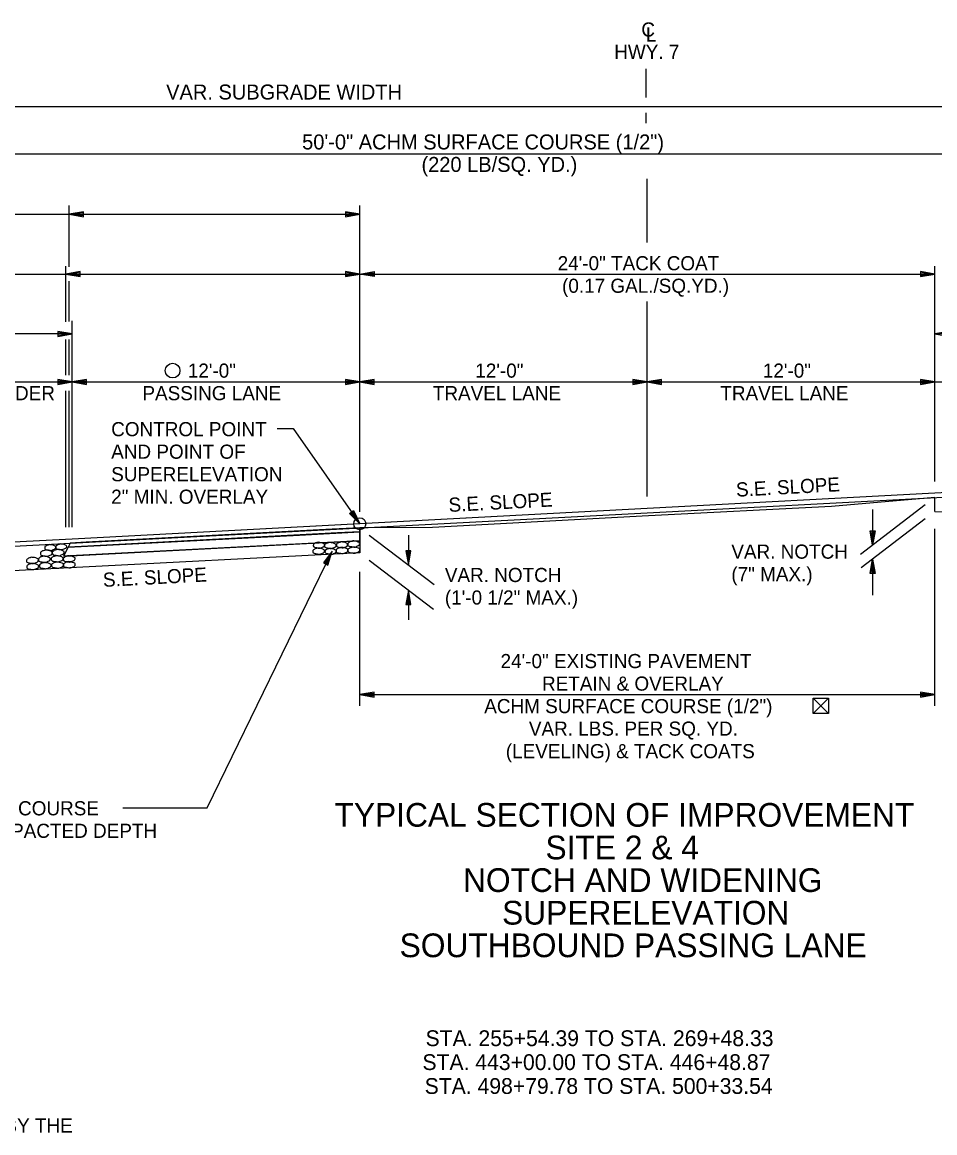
# Model space of a CAD drawing. Extents: x 1398183 to 1398373, y 1967240 to 1968889.
# Drawn here: x 1398222.36 to 1398260.45, y 1968068.4 to 1968114.76 of the extents above; entities that cross this region are included whole.
import ezdxf

# ---------------------------------------------------------------- set-up
doc = ezdxf.new("R2010")
doc.units = 0
for name, color, linetype in [('1', 7, 'Continuous'), ('10', 7, 'Continuous'), ('19', 7, 'Continuous'), ('42', 7, 'Continuous'), ('7', 7, 'Continuous'), ('Level 1', 7, 'Continuous'), ('Level 9', 7, 'Continuous')]:
    doc.layers.add(name, color=color, linetype=linetype)

# ---------------------------------------------------------------- blocks, each defined once
blk = doc.blocks.new('ROCKS')
at = {"layer": '1'}
blk.add_spline([(0.013, 0.06), (0.053, 0.053), (0.107, 0.033), (0.133, 0.013), (0.133, -0.007), (0.12, -0.033), (0.107, -0.04), (0.073, -0.053), (0.033, -0.067), (0.013, -0.067), (-0.02, -0.06), (-0.06, -0.053), (-0.087, -0.047), (-0.113, -0.02), (-0.113, -0.007), (-0.107, 0.02), (-0.087, 0.033), (-0.067, 0.047), (-0.033, 0.053), (-0.02, 0.06), (0.013, 0.06)], degree=3, dxfattribs=at)

msp = doc.modelspace()

# ---------------------------------------------------------------- linework, layer by layer
at = {"layer": '10'}
for p, q in [((1398256.012, 1968086.545), (1398255.37, 1968085.904)), ((1398255.37, 1968086.545), (1398256.012, 1968085.904)), ((1398255.63, 1968085.904), (1398255.619, 1968085.904))]:
    msp.add_line(p, q, dxfattribs=at)
msp.add_lwpolyline([(1398255.619, 1968085.904), (1398255.37, 1968085.904), (1398255.37, 1968086.545), (1398256.012, 1968086.545), (1398256.012, 1968085.904), (1398255.63, 1968085.904)], dxfattribs=at)
msp.add_circle((1398228.634, 1968100.217), 0.306, dxfattribs=at)
at = {"layer": '19'}
for p, q in [((1398212.441, 1968111.247), (1398274.281, 1968111.247)), ((1398268.448, 1968109.247), (1398218.448, 1968109.247)), ((1398224.318, 1968104.556), (1398224.318, 1968107.106)), ((1398236.446, 1968094.324), (1398236.446, 1968107.106)), ((1398206.204, 1968106.747), (1398236.446, 1968106.747)), ((1398224.918, 1968106.852), (1398224.318, 1968106.747)), ((1398224.318, 1968106.747), (1398224.918, 1968106.642)), ((1398224.918, 1968106.797), (1398224.478, 1968106.762)), ((1398224.478, 1968106.732), (1398224.918, 1968106.692)), ((1398224.918, 1968106.642), (1398224.918, 1968106.852)), ((1398235.846, 1968106.852), (1398235.846, 1968106.642)), ((1398236.446, 1968106.747), (1398235.846, 1968106.852)), ((1398236.286, 1968106.762), (1398235.846, 1968106.797)), ((1398235.846, 1968106.642), (1398236.446, 1968106.747)), ((1398235.846, 1968106.692), (1398236.286, 1968106.732)), ((1398207.393, 1968104.247), (1398260.446, 1968104.247)), ((1398224.179, 1968102.248), (1398224.18, 1968104.572)), ((1398224.78, 1968104.352), (1398224.18, 1968104.247)), ((1398224.18, 1968104.247), (1398224.78, 1968104.142)), ((1398224.78, 1968104.297), (1398224.34, 1968104.262)), ((1398224.34, 1968104.232), (1398224.78, 1968104.192)), ((1398224.78, 1968104.142), (1398224.78, 1968104.352)), ((1398235.846, 1968104.352), (1398235.846, 1968104.142)), ((1398236.446, 1968104.247), (1398235.846, 1968104.352)), ((1398236.286, 1968104.262), (1398235.846, 1968104.297)), ((1398235.846, 1968104.142), (1398236.446, 1968104.247)), ((1398235.846, 1968104.192), (1398236.286, 1968104.232)), ((1398236.446, 1968104.247), (1398237.046, 1968104.352)), ((1398237.046, 1968104.142), (1398236.446, 1968104.247)), ((1398236.606, 1968104.262), (1398237.046, 1968104.297)), ((1398237.046, 1968104.192), (1398236.606, 1968104.232)), ((1398237.046, 1968104.352), (1398237.046, 1968104.142)), ((1398259.846, 1968104.352), (1398259.846, 1968104.142)), ((1398260.446, 1968104.247), (1398259.846, 1968104.352)), ((1398260.286, 1968104.262), (1398259.846, 1968104.297)), ((1398259.846, 1968104.142), (1398260.446, 1968104.247)), ((1398259.846, 1968104.192), (1398260.286, 1968104.232)), ((1398260.446, 1968095.596), (1398260.446, 1968104.572)), ((1398224.318, 1968102.266), (1398224.318, 1968103.949)), ((1398224.446, 1968093.688), (1398224.446, 1968102.294)), ((1398224.446, 1968101.747), (1398206.446, 1968101.747)), ((1398223.846, 1968101.852), (1398223.846, 1968101.642)), ((1398224.446, 1968101.747), (1398223.846, 1968101.852)), ((1398224.286, 1968101.762), (1398223.846, 1968101.797)), ((1398223.846, 1968101.642), (1398224.446, 1968101.747)), ((1398223.846, 1968101.692), (1398224.286, 1968101.732)), ((1398224.181, 1968100.029), (1398224.181, 1968101.517)), ((1398224.318, 1968100.032), (1398224.318, 1968101.52)), ((1398261.046, 1968101.852), (1398260.446, 1968101.747)), ((1398284.446, 1968101.747), (1398260.446, 1968101.747)), ((1398260.446, 1968101.747), (1398261.046, 1968101.642)), ((1398218.445, 1968099.747), (1398224.445, 1968099.747)), ((1398223.846, 1968099.852), (1398223.846, 1968099.642)), ((1398224.446, 1968099.747), (1398223.846, 1968099.852)), ((1398224.286, 1968099.762), (1398223.846, 1968099.797)), ((1398223.846, 1968099.642), (1398224.446, 1968099.747)), ((1398223.846, 1968099.692), (1398224.286, 1968099.732)), ((1398225.046, 1968099.852), (1398224.446, 1968099.747)), ((1398224.446, 1968099.747), (1398225.046, 1968099.642)), ((1398224.446, 1968099.747), (1398236.446, 1968099.747)), ((1398225.046, 1968099.797), (1398224.606, 1968099.762)), ((1398224.606, 1968099.732), (1398225.046, 1968099.692)), ((1398225.046, 1968099.642), (1398225.046, 1968099.852)), ((1398235.846, 1968099.852), (1398235.846, 1968099.642)), ((1398236.446, 1968099.747), (1398235.846, 1968099.852)), ((1398236.286, 1968099.762), (1398235.846, 1968099.797)), ((1398235.846, 1968099.642), (1398236.446, 1968099.747)), ((1398235.846, 1968099.692), (1398236.286, 1968099.732)), ((1398237.046, 1968099.852), (1398236.446, 1968099.747)), ((1398236.446, 1968099.747), (1398237.046, 1968099.642)), ((1398236.446, 1968099.747), (1398248.446, 1968099.747)), ((1398237.046, 1968099.797), (1398236.606, 1968099.762)), ((1398236.606, 1968099.732), (1398237.046, 1968099.692)), ((1398237.046, 1968099.642), (1398237.046, 1968099.852)), ((1398247.846, 1968099.852), (1398247.846, 1968099.642)), ((1398248.446, 1968099.747), (1398247.846, 1968099.852)), ((1398248.286, 1968099.762), (1398247.846, 1968099.797)), ((1398247.846, 1968099.642), (1398248.446, 1968099.747)), ((1398247.846, 1968099.692), (1398248.286, 1968099.732)), ((1398249.046, 1968099.852), (1398248.446, 1968099.747)), ((1398248.446, 1968099.747), (1398249.046, 1968099.642)), ((1398248.446, 1968099.747), (1398260.446, 1968099.747)), ((1398249.046, 1968099.797), (1398248.606, 1968099.762)), ((1398248.606, 1968099.732), (1398249.046, 1968099.692)), ((1398249.046, 1968099.642), (1398249.046, 1968099.852)), ((1398259.846, 1968099.852), (1398259.846, 1968099.642)), ((1398260.446, 1968099.747), (1398259.846, 1968099.852)), ((1398260.286, 1968099.762), (1398259.846, 1968099.797)), ((1398259.846, 1968099.642), (1398260.446, 1968099.747)), ((1398259.846, 1968099.692), (1398260.286, 1968099.732)), ((1398260.446, 1968099.747), (1398268.446, 1968099.747)), ((1398224.181, 1968093.688), (1398224.181, 1968099.376)), ((1398224.318, 1968093.688), (1398224.318, 1968099.373)), ((1398260.049, 1968094.611), (1398257.346, 1968092.542)), ((1398260.446, 1968094.338), (1398260.446, 1968094.921)), ((1398236.016, 1968094.255), (1398236.187, 1968094.374)), ((1398236.446, 1968093.824), (1398236.016, 1968094.255)), ((1398236.346, 1968093.948), (1398236.063, 1968094.282)), ((1398236.152, 1968094.345), (1398236.366, 1968093.964)), ((1398236.187, 1968094.374), (1398236.446, 1968093.824)), ((1398260.049, 1968094.034), (1398257.367, 1968091.981)), ((1398257.848, 1968094.426), (1398257.848, 1968092.926)), ((1398260.446, 1968094.338), (1398274.28, 1968094.061)), ((1398236.446, 1968093.655), (1398236.446, 1968093.488)), ((1398260.446, 1968086.222), (1398260.446, 1968093.612)), ((1398236.446, 1968093.113), (1398224.086, 1968092.469)), ((1398224.276, 1968092.848), (1398236.446, 1968093.488)), ((1398235.522, 1968093.441), (1398224.833, 1968092.878)), ((1398236.446, 1968093.488), (1398235.522, 1968093.441)), ((1398235.542, 1968093.066), (1398236.446, 1968093.113)), ((1398236.446, 1968093.488), (1398236.446, 1968093.113)), ((1398236.446, 1968093.113), (1398236.446, 1968093.488)), ((1398236.446, 1968093.113), (1398236.446, 1968092.613)), ((1398236.843, 1968093.351), (1398239.545, 1968091.283)), ((1398238.474, 1968093.352), (1398238.474, 1968092.102)), ((1398257.743, 1968093.526), (1398257.953, 1968093.526)), ((1398257.848, 1968092.926), (1398257.743, 1968093.526)), ((1398257.833, 1968093.086), (1398257.793, 1968093.526)), ((1398257.953, 1968093.526), (1398257.848, 1968092.926)), ((1398257.898, 1968093.526), (1398257.863, 1968093.086)), ((1398224.276, 1968092.848), (1398224.086, 1968092.469)), ((1398224.361, 1968093.018), (1398224.276, 1968092.848)), ((1398230.081, 1968081.974), (1398235.293, 1968092.681)), ((1398235.293, 1968092.681), (1398234.929, 1968092.192)), ((1398235.116, 1968092.1), (1398235.293, 1968092.681)), ((1398238.579, 1968092.702), (1398238.369, 1968092.702)), ((1398238.369, 1968092.702), (1398238.474, 1968092.102)), ((1398238.424, 1968092.702), (1398238.459, 1968092.262)), ((1398238.474, 1968092.102), (1398238.579, 1968092.702)), ((1398238.489, 1968092.262), (1398238.529, 1968092.702)), ((1398234.929, 1968092.192), (1398235.116, 1968092.1)), ((1398235.21, 1968092.545), (1398234.978, 1968092.171)), ((1398235.072, 1968092.123), (1398235.235, 1968092.532)), ((1398236.843, 1968092.309), (1398239.524, 1968090.257)), ((1398257.743, 1968091.749), (1398257.848, 1968092.349)), ((1398257.793, 1968091.749), (1398257.833, 1968092.189)), ((1398257.848, 1968092.349), (1398257.953, 1968091.749)), ((1398257.848, 1968092.349), (1398257.848, 1968090.849)), ((1398257.863, 1968092.189), (1398257.898, 1968091.749)), ((1398236.446, 1968086.222), (1398236.446, 1968091.822)), ((1398257.953, 1968091.749), (1398257.743, 1968091.749)), ((1398238.474, 1968091.06), (1398238.369, 1968090.46)), ((1398238.459, 1968090.9), (1398238.424, 1968090.46)), ((1398238.579, 1968090.46), (1398238.474, 1968091.06)), ((1398238.474, 1968091.06), (1398238.474, 1968089.81)), ((1398238.529, 1968090.46), (1398238.489, 1968090.9)), ((1398238.369, 1968090.46), (1398238.579, 1968090.46)), ((1398237.046, 1968086.797), (1398236.446, 1968086.692)), ((1398236.446, 1968086.692), (1398237.046, 1968086.587)), ((1398236.446, 1968086.692), (1398260.446, 1968086.692)), ((1398237.046, 1968086.742), (1398236.606, 1968086.707)), ((1398236.606, 1968086.677), (1398237.046, 1968086.637)), ((1398237.046, 1968086.587), (1398237.046, 1968086.797)), ((1398259.846, 1968086.797), (1398259.846, 1968086.587)), ((1398260.446, 1968086.692), (1398259.846, 1968086.797)), ((1398260.286, 1968086.707), (1398259.846, 1968086.742)), ((1398259.846, 1968086.587), (1398260.446, 1968086.692)), ((1398259.846, 1968086.637), (1398260.286, 1968086.677)), ((1398226.553, 1968081.974), (1398230.081, 1968081.974))]:
    msp.add_line(p, q, dxfattribs=at)
for points in [[(1398232.998, 1968097.797), (1398233.664, 1968097.797), (1398236.446, 1968093.824)], [(1398268.446, 1968095.52), (1398260.446, 1968095.096), (1398248.446, 1968094.46), (1398236.446, 1968093.824), (1398224.446, 1968093.188), (1398218.446, 1968092.87)], [(1398224.086, 1968092.469), (1398224.654, 1968092.5), (1398235.542, 1968093.066)], [(1398224.833, 1968092.878), (1398224.276, 1968092.848), (1398224.086, 1968092.469)], [(1398236.446, 1968092.613), (1398224.086, 1968091.969), (1398212.408, 1968091.36)]]:
    msp.add_lwpolyline(points, dxfattribs=at)
for points in [[(1398218.361, 1968092.7), (1398224.361, 1968093.018), (1398248.436, 1968094.287), (1398260.531, 1968094.925), (1398268.531, 1968095.35), (1398268.446, 1968095.52), (1398260.446, 1968095.096), (1398248.446, 1968094.46), (1398224.446, 1968093.188), (1398218.446, 1968092.87)], [(1398224.361, 1968093.018), (1398224.276, 1968092.848), (1398225.085, 1968092.89), (1398233.928, 1968093.356), (1398236.446, 1968093.488), (1398236.446, 1968093.655), (1398235.287, 1968093.594), (1398225.026, 1968093.052)]]:
    msp.add_lwpolyline(points, close=True, dxfattribs=at)
at = {"layer": '42'}
msp.add_lwpolyline([(1398260.446, 1968094.915), (1398256.136, 1968094.542), (1398248.499, 1968094.153), (1398239.478, 1968093.669), (1398236.454, 1968093.657), (1398236.446, 1968093.657)], dxfattribs=at)
at = {"layer": '7'}
for p, q in [((1398248.403, 1968111.612), (1398248.403, 1968112.816)), ((1398248.404, 1968110.552), (1398248.404, 1968110.98)), ((1398248.445, 1968105.559), (1398248.445, 1968108.228)), ((1398248.446, 1968094.96), (1398248.445, 1968103.098))]:
    msp.add_line(p, q, dxfattribs=at)
at = {"layer": 'Level 9'}
msp.add_circle((1398236.446, 1968093.823), 0.25, dxfattribs=at)

# ---------------------------------------------------------------- block references
at = {"layer": 'Level 1'}
for p, xscale, yscale, rotation in [((1398236.172, 1968092.986), 2.011654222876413, 2.011654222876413, 1.8263814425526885), ((1398223.342, 1968092.602), 2.011654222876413, 2.011654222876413, 1.8263814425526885), ((1398223.508, 1968092.839), 1.8771740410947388, 1.8771740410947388, 1.8263814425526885), ((1398223.838, 1968092.626), 2.011654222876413, 2.011654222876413, 1.8263814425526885), ((1398223.838, 1968092.626), 2.011654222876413, 2.011654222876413, 1.8263814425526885), ((1398223.967, 1968092.868), 1.849824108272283, 1.849824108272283, 1.826381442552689), ((1398234.712, 1968092.688), 1.9974694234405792, 1.9974694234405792, -0.17361855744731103), ((1398234.721, 1968092.935), 1.907051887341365, 1.9070518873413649, -0.173618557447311), ((1398235.197, 1968092.923), 1.9598639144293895, 1.959863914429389, -0.173618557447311), ((1398235.209, 1968092.679), 1.890205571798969, 1.8902055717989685, -0.17361855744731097), ((1398235.683, 1968092.714), 2.011654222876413, 2.011654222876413, 1.8263814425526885), ((1398235.685, 1968092.95), 1.9008744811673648, 1.900874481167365, 1.8263814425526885), ((1398236.178, 1968092.729), 2.011654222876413, 2.011654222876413, 1.8263814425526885), ((1398222.762, 1968092.302), 2.011654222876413, 2.011654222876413, 1.8263814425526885), ((1398222.776, 1968092.044), 2.011654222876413, 2.011654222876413, 1.8263814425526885), ((1398223.258, 1968092.348), 2.011654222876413, 2.011654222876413, 1.8263814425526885), ((1398223.299, 1968092.084), 2.011654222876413, 2.011654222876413, 1.8263814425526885), ((1398223.793, 1968092.365), 2.011654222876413, 2.011654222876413, 1.8263814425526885), ((1398223.81, 1968092.105), 2.011654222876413, 2.011654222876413, 1.8263814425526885), ((1398224.295, 1968092.362), 2.011654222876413, 2.011654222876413, 1.8263814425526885), ((1398224.303, 1968092.12), 2.011654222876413, 2.011654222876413, 1.8263814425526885)]:
    msp.add_blockref('ROCKS', p, dxfattribs=dict(at, xscale=xscale, yscale=yscale, rotation=rotation))

# ---------------------------------------------------------------- texts
at = {"layer": '10'}
for s, height, p in [('12\'-0"', 0.59, (1398229.268, 1968099.922)), ('12\'-0"', 0.59, (1398241.268, 1968099.922)), ('12\'-0"', 0.59, (1398253.268, 1968099.922)), ('SHOULDER', 0.59, (1398219.339, 1968098.982)), ('PASSING LANE', 0.59001, (1398227.375, 1968098.982)), ('TRAVEL LANE', 0.59001, (1398239.496, 1968098.982)), ('TRAVEL LANE', 0.59001, (1398251.496, 1968098.982)), ('CONTROL POINT', 0.59001, (1398226.071, 1968097.479)), ('AND POINT OF ', 0.59001, (1398226.071, 1968096.539)), ('SUPERELEVATION', 0.59001, (1398226.071, 1968095.599)), ('2" MIN. OVERLAY', 0.59001, (1398226.071, 1968094.659)), ('VAR. NOTCH', 0.59, (1398251.954, 1968092.367)), ('VAR. NOTCH', 0.59, (1398239.998, 1968091.393)), ('(7" MAX.)', 0.59, (1398251.954, 1968091.427)), ('(1\'-0 1/2" MAX.)', 0.59001, (1398239.998, 1968090.453))]:
    msp.add_text(s, height=height, dxfattribs=at).set_placement(p)
for s, rotation, p in [('24\'-0" EXISTING PAVEMENT', 0, (1398242.322, 1968087.799)), ('RETAIN & OVERLAY', 0, (1398244.052, 1968086.859)), ('ACHM SURFACE COURSE (1/2")', 0, (1398241.641, 1968085.919)), ('VAR. LBS. PER SQ. YD.', 0, (1398243.504, 1968084.979)), ('(LEVELING) & TACK COATS', 0, (1398242.542, 1968084.039)), ('TO BE USED IF AND WHERE DIRECTED BY THE ', 360, (1398206.406, 1968068.413))]:
    msp.add_text(s, height=0.59001, rotation=rotation, dxfattribs=at).set_placement(p)
at = {"layer": '19'}
for s, height, p in [('C', 0.59, (1398248.198, 1968114.161)), ('L', 0.59, (1398248.387, 1968113.951)), ('HWY. 7', 0.59, (1398247.067, 1968113.231)), ('VAR. SUBGRADE WIDTH', 0.625, (1398228.366, 1968111.534)), ('50\'-0" ACHM SURFACE COURSE (1/2")', 0.625, (1398234.041, 1968109.45)), ('(220 LB/SQ. YD.)', 0.625, (1398239.022, 1968108.512)), ('TYPICAL SECTION OF IMPROVEMENT', 0.98999, (1398235.392, 1968081.179)), ('SITE 2 & 4', 0.99, (1398244.197, 1968079.818)), ('NOTCH AND WIDENING', 0.98999, (1398240.755, 1968078.456)), ('SUPERELEVATION', 0.98999, (1398242.385, 1968077.095)), ('SOUTHBOUND PASSING LANE', 0.98999, (1398238.109, 1968075.734)), ('STA. 255+54.39 TO STA. 269+48.33', 0.65999, (1398239.192, 1968072.021)), ('STA. 443+00.00 TO STA. 446+48.87', 0.65999, (1398239.062, 1968071.023)), ('STA. 498+79.78 TO STA. 500+33.54', 0.65999, (1398239.155, 1968070.026))]:
    msp.add_text(s, height=height, dxfattribs=at).set_placement(p)
for s, height, rotation, p in [('S.E. SLOPE', 0.59, 3.0338, (1398252.166, 1968094.952)), ('S.E. SLOPE', 0.59, 3.0338, (1398240.166, 1968094.316)), ('S.E. SLOPE', 0.59, 3.0338, (1398225.743, 1968091.187)), ('AGGREGATE BASE COURSE', 0.59001, 360, (1398214.643, 1968081.654)), ('(CLASS 7) - 6" COMPACTED DEPTH', 0.59001, 360, (1398214.643, 1968080.714))]:
    msp.add_text(s, height=height, rotation=rotation, dxfattribs=at).set_placement(p)
at = {"layer": '42'}
for s, p in [('24\'-0" TACK COAT', (1398244.705, 1968104.405)), ('(0.17 GAL./SQ.YD.)', (1398244.889, 1968103.465))]:
    msp.add_text(s, height=0.59001, rotation=360, dxfattribs=at).set_placement(p)

doc.saveas('drawing.dxf')
